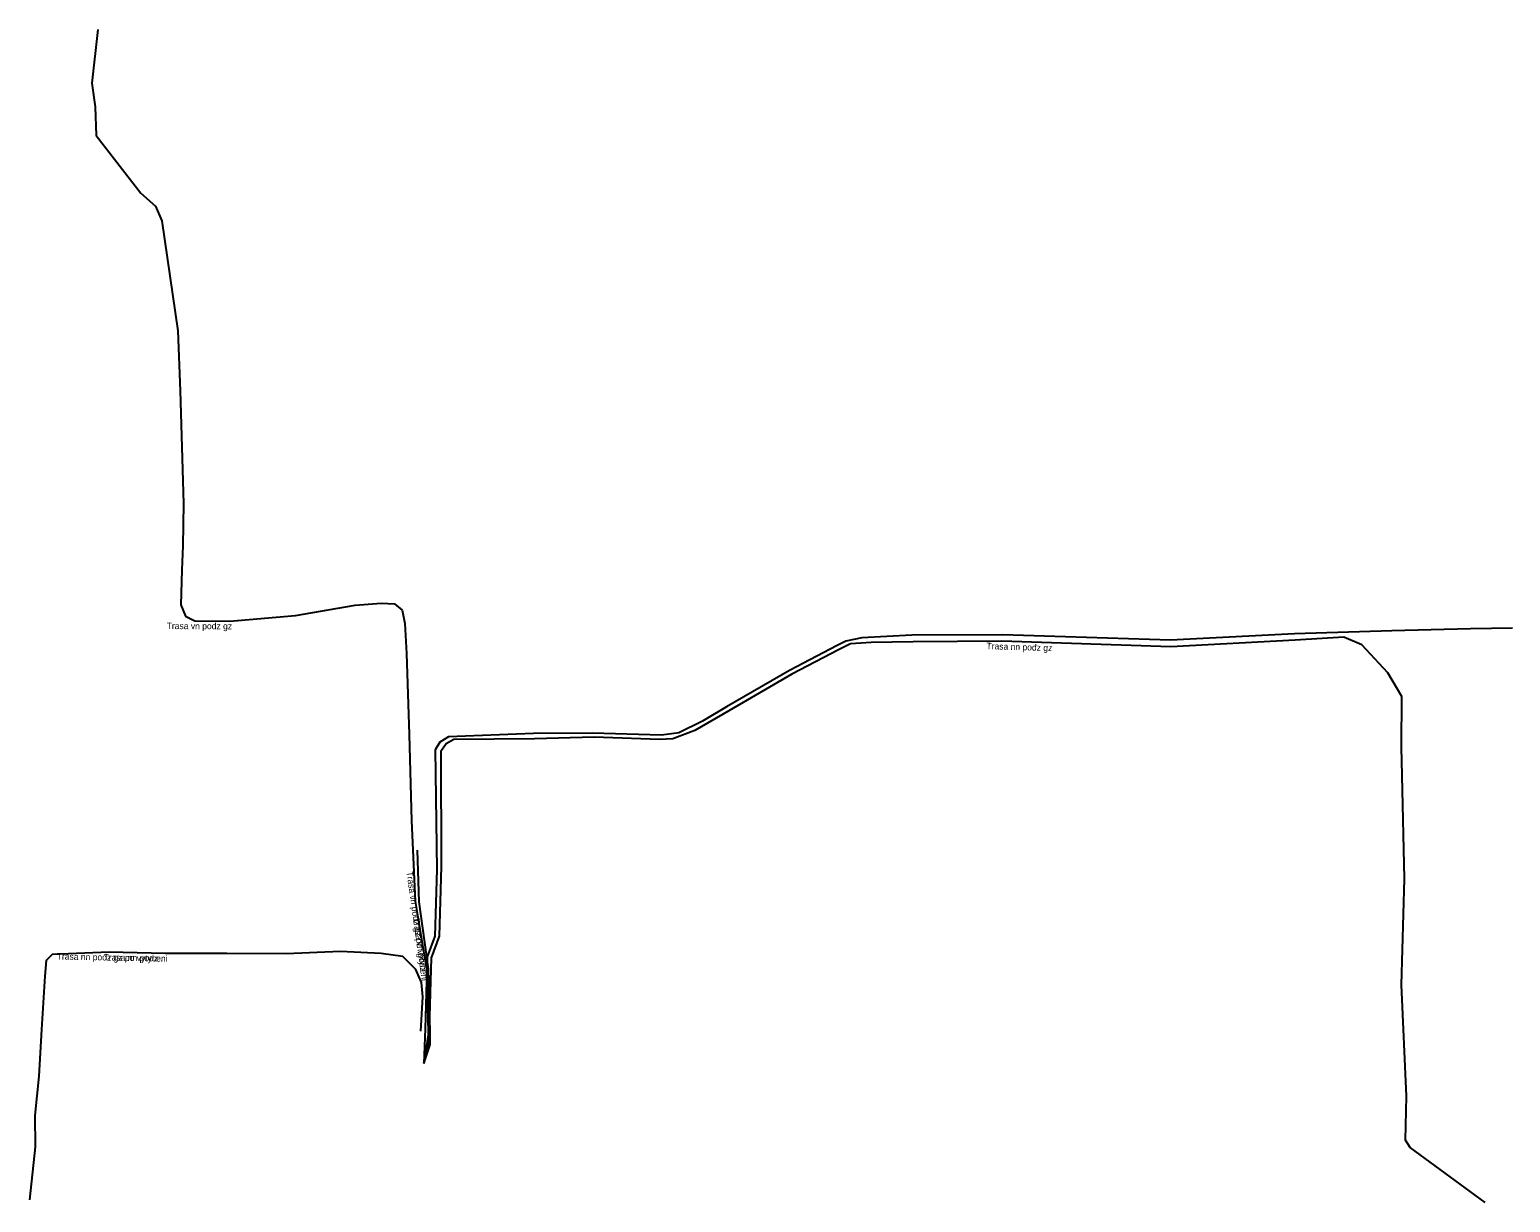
# Model space of a CAD drawing. Extents: x -473912 to -473677, y -1106157 to -1105684.
# Drawn here: x -473875.2 to -473759, y -1105776.3 to -1105684.3 of the extents above; entities that cross this region are included whole.
import ezdxf

# ---------------------------------------------------------------- set-up
doc = ezdxf.new("R2010")
doc.units = 0
for name, color, linetype in [('Popiskový text - Ostatní atributy Trasy', 7, 'Continuous'), ('Spojnice NN', 7, 'Continuous'), ('Spojnice VN', 7, 'Continuous')]:
    doc.layers.add(name, color=color, linetype=linetype)

msp = doc.modelspace()

# ---------------------------------------------------------------- linework, layer by layer
at = {"layer": 'Spojnice NN'}
for points in [[(-473758.89, -1105731.28), (-473762.17, -1105731.33), (-473768.33, -1105731.5), (-473775.97, -1105731.73), (-473785.71, -1105732.22), (-473798.87, -1105731.8), (-473805.99, -1105731.84), (-473809.92, -1105732.04), (-473811.17, -1105732.3), (-473811.85, -1105732.63), (-473815.59, -1105734.6), (-473820.52, -1105737.46), (-473822.41, -1105738.56), (-473824.27, -1105739.48), (-473825.62, -1105739.68), (-473831.03, -1105739.51), (-473835.67, -1105739.54), (-473842.33, -1105739.81), (-473843, -1105740.21), (-473843.36, -1105740.82), (-473843.23, -1105750.21), (-473843.4, -1105755.43), (-473844.01, -1105757.06), (-473844.16, -1105762.71), (-473844.26, -1105765.41)], [(-473761.02, -1105776.31), (-473766.91, -1105772), (-473767.27, -1105771.44), (-473767.19, -1105767.97), (-473767.58, -1105759.24), (-473767.36, -1105750.93), (-473767.53, -1105742.83), (-473767.58, -1105740.61), (-473767.57, -1105736.63), (-473768.65, -1105734.79), (-473770.69, -1105732.59), (-473772.11, -1105731.99), (-473775.93, -1105732.22), (-473785.67, -1105732.73), (-473798.93, -1105732.31), (-473805.89, -1105732.35), (-473809.19, -1105732.41), (-473810.8, -1105732.52), (-473811.69, -1105732.96), (-473815.39, -1105734.88), (-473820.34, -1105737.76), (-473823.01, -1105739.31), (-473824.74, -1105739.97), (-473825.78, -1105740), (-473830.9, -1105739.84), (-473835.57, -1105739.95), (-473841.92, -1105740), (-473842.51, -1105740.35), (-473842.92, -1105740.94), (-473842.89, -1105749.97), (-473843.07, -1105755.44), (-473843.69, -1105757.12), (-473843.84, -1105762.64), (-473844.26, -1105765.41)], [(-473844.49, -1105762.87), (-473844.34, -1105760.19), (-473844.45, -1105759.07), (-473844.88, -1105758.05), (-473845.9, -1105757.02), (-473847.6, -1105756.78), (-473850.79, -1105756.63), (-473855.05, -1105756.83), (-473859.72, -1105756.79), (-473864.56, -1105756.78), (-473868.93, -1105756.69), (-473873.42, -1105756.87), (-473873.89, -1105757.34), (-473873.99, -1105758.57), (-473874.24, -1105762.75), (-473874.47, -1105766.41), (-473874.76, -1105769.49), (-473874.74, -1105771.96), (-473875.18, -1105776.12)], [(-473844.49, -1105762.87), (-473844.34, -1105760.19), (-473844.45, -1105759.07), (-473844.88, -1105758.05), (-473845.9, -1105757.02), (-473847.6, -1105756.78), (-473850.79, -1105756.63), (-473855.05, -1105756.83), (-473859.72, -1105756.79), (-473864.56, -1105756.78), (-473868.93, -1105756.69), (-473873.42, -1105756.87), (-473873.89, -1105757.34), (-473873.99, -1105758.57), (-473874.24, -1105762.75), (-473874.47, -1105766.41), (-473874.76, -1105769.49), (-473874.74, -1105771.96), (-473875.18, -1105776.12)]]:
    msp.add_lwpolyline(points, dxfattribs=at)
at = {"layer": 'Spojnice VN'}
for points in [[(-473869.84, -1105684.34), (-473870.29, -1105688.54), (-473870.03, -1105690.4), (-473869.96, -1105692.65), (-473866.45, -1105697.16), (-473865.3, -1105698.19), (-473864.82, -1105699.33), (-473863.55, -1105707.97), (-473863.37, -1105712.66), (-473863.12, -1105721.5), (-473863.16, -1105724.82), (-473863.23, -1105726.71), (-473863.32, -1105729.44), (-473862.96, -1105730.33), (-473862.23, -1105730.71), (-473859.48, -1105730.72), (-473854.33, -1105730.29), (-473849.66, -1105729.47), (-473847.62, -1105729.33), (-473846.55, -1105729.36), (-473845.95, -1105729.88), (-473845.75, -1105730.92), (-473845.61, -1105733.26), (-473845.4, -1105739.63), (-473845.24, -1105746.38), (-473844.94, -1105752.7), (-473844.05, -1105758.01), (-473843.93, -1105762.93), (-473843.94, -1105763.93), (-473844.26, -1105765.41)], [(-473844.26, -1105765.41), (-473843.76, -1105763.93), (-473843.76, -1105762.92), (-473843.9, -1105758), (-473844.64, -1105752.74), (-473844.77, -1105748.69)], [(-473844.26, -1105765.41), (-473843.76, -1105763.93), (-473843.76, -1105762.92), (-473843.9, -1105758), (-473844.64, -1105752.74), (-473844.77, -1105748.69)]]:
    msp.add_lwpolyline(points, dxfattribs=at)

# ---------------------------------------------------------------- texts
at = {"layer": 'Popiskový text - Ostatní atributy Trasy'}
for s, rotation, p in [('Trasa vn podz gz', 359.7917, (-473864.43, -1105731.35)), ('Trasa nn podz gz', 358.1858, (-473800.14, -1105732.92)), ('Trasa vn podz gz po vytyceni', 278.0081, (-473845.63, -1105750.39)), ('Trasa vn podz', 278.0081, (-473845.11, -1105754.04)), ('Trasa nn podz gz po vytyceni', 358.8202, (-473873.06, -1105757.26)), ('Trasa nn podz', 358.8202, (-473869.38, -1105757.33))]:
    msp.add_text(s, height=0.5, rotation=rotation, dxfattribs=at).set_placement(p)

doc.saveas('drawing.dxf')
